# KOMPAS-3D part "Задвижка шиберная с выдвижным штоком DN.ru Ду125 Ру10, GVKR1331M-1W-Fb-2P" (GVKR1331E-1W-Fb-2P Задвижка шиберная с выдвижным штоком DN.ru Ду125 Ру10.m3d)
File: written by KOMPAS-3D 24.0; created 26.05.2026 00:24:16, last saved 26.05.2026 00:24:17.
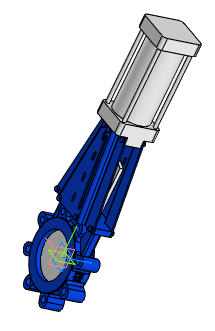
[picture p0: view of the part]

Document properties: Автор: R2D2; Полное имя файла: E:\Работа\Зайцев\GVKR1331M-1W-Fb-2P Задвижка шиберная с выдвижным штоком DN.ru Ду50-300 Ру16-10-6 с пневмоприводом\исходные материалы\DN125\DN125\GVKR1331E-1W-Fb-2P Задвижка шиберная с выдвижным штоком DN.ru Ду125 Ру10.m3d

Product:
- Part/product: Задвижка шиберная с выдвижным штоком DN.ru Ду125 Ру10  | designation GVKR1331M-1W-Fb-2P
    Масса: 16
    Раздел спецификации: Прочие изделия
    Примечание: D040-08795

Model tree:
1. Операция без истории:1

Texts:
  GVKR1331M-1W-Fb-2P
